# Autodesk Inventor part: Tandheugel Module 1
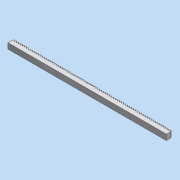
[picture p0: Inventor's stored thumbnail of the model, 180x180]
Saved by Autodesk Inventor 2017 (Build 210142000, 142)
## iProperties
Created: 2018-02
Part Number: Tandheugel Module 1
Material: Generic
Document SubType Name: Modeling
Designer: J. van de Ven
Density: 1 g/cm^3
Appearance: Snow
Author: J. van de Ven
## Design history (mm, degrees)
sketch "Sketch1"
  geometry: L1 (-31.654, 0)-(0, 0); L2 (0, 0)-(0, 20.626); L3 (-125, 4.45)-(125, 4.45); L4 (125, 4.45)-(125, -4.45); L5 (125, -4.45)-(-125, -4.45); L6 (-125, -4.45)-(-125, 4.45); 2 further points
  constraints: 12 end point, 2 coincident, 2 horizontal, 2 parallel, 2 perpendicular, 3 other
  dimensions: "d0" = 250 distance of L3.start L3.end; "d2" = 8.9 distance of L5.end L3.start
extrude "Extrusion1" new body sketch "Sketch1" stored distance "d4" = 9; taper "d5" = 0 deg
sketch "Sketch2"
  geometry: L1 (-125, 4.45)-(-125, -4.45) reference; L2 (-125, 2.45)-(125, 2.45); L3 (125, -4.45)-(125, 4.45) reference; L4 (125, 4.45)-(-125, 4.45) reference; L5 (-125, 2.45)-(-124.65, 2.45); L6 (-124.65, 2.45)-(-123.787, 4.45); L7 (-123.787, 4.45)-(-123.088, 4.45); L8 (-123.088, 4.45)-(-122.225, 2.45); L9 (-123.438, 4.45)-(-123.438, 2.45); L10 (-125, 2.45)-(-125, 5.194); L11 (-125, 5.194)-(-121.875, 5.194); L12 (-122.225, 2.45)-(-121.875, 2.45); L13 (-121.875, 2.45)-(-121.875, 5.194); 1 further point
  constraints: 20 end point, 9 point on line, 2 perpendicular, 1 horizontal, 1 midpoint, 1 vertical, 1 other
  dimensions: "d6" = 2 distance between parallel lines of L2 L4; "d7" = 0.35 distance of L2.start L5.end; "d8" = 0.7 distance of L6.end L7.end; "d15" = 0.35 distance of L12.end L8.end (= d7); "d16" = 3.125 distance between parallel lines of L13 L1
extrude "Extrusion2" cut sketch "Sketch2" distance "d10" = 9; taper "d11" = 0 deg
body "Solid1"
pattern_linear "Rectangular Pattern1" dims "d14" = 3.125
